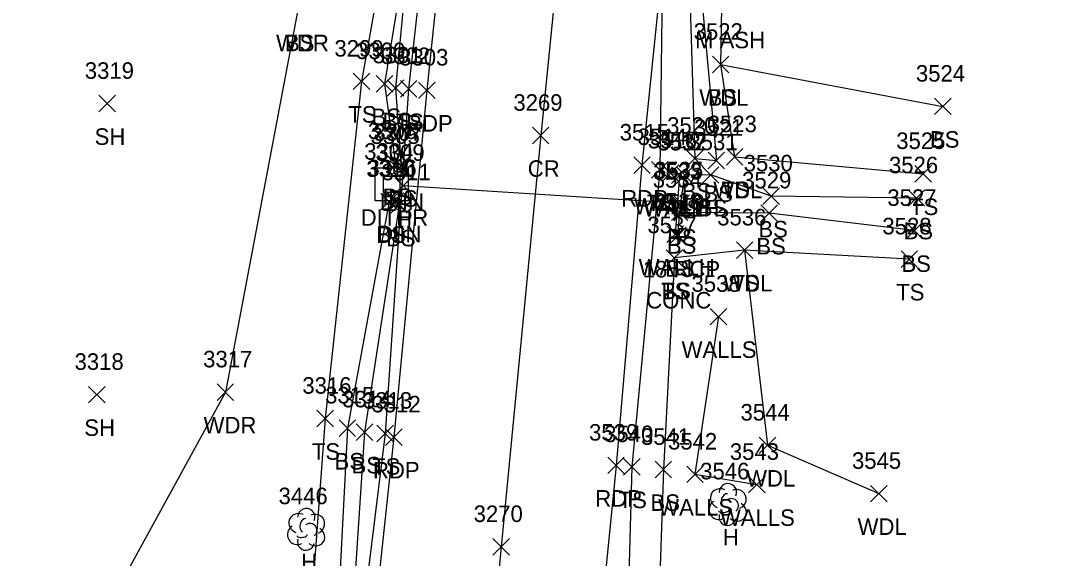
# Model space of a CAD drawing. Extents: x 1678863 to 1683592, y 407783 to 418211.
# Drawn here: x 1680318.1 to 1680442.9, y 414605.2 to 414670.3 of the extents above; entities that cross this region are included whole.
import ezdxf

# ---------------------------------------------------------------- set-up
doc = ezdxf.new("R2010")
doc.units = 0
for name, color, linetype in [('D_A', 7, 'Continuous'), ('D_C', 7, 'Continuous'), ('D_I', 7, 'Continuous'), ('D_TIC', 7, 'Continuous'), ('DCP', 7, 'Continuous'), ('DHW', 7, 'Continuous'), ('DS', 7, 'Continuous'), ('L_A', 7, 'Continuous'), ('L_C', 7, 'Continuous'), ('L_I', 7, 'Continuous'), ('L_TIC', 7, 'Continuous'), ('LAWA', 7, 'Continuous'), ('LELB', 7, 'Continuous'), ('LTD', 7, 'Continuous'), ('LWS', 7, 'Continuous'), ('P_A', 7, 'Continuous'), ('P_I', 7, 'Continuous'), ('P_TIC', 7, 'Continuous'), ('PET', 7, 'Continuous'), ('PRC', 7, 'Continuous')]:
    doc.layers.add(name, color=color, linetype=linetype)

msp = doc.modelspace()

# ---------------------------------------------------------------- linework, layer by layer
at = {"layer": 'D_TIC'}
for points in [[(1680362.81, 414651.36), (1680364.81, 414653.36)], [(1680364.81, 414651.36), (1680362.81, 414653.36)], [(1680395.77, 414650.82), (1680397.77, 414652.82)], [(1680397.77, 414650.82), (1680395.77, 414652.82)], [(1680396.87, 414650.57), (1680398.87, 414652.57)], [(1680398.87, 414650.57), (1680396.87, 414652.57)], [(1680363.4, 414649.31), (1680365.4, 414651.31)], [(1680365.4, 414649.31), (1680363.4, 414651.31)], [(1680362.5, 414647.45), (1680364.5, 414649.45)], [(1680364.5, 414647.45), (1680362.5, 414649.45)], [(1680397.05, 414647.2), (1680399.05, 414649.2)], [(1680399.05, 414647.2), (1680397.05, 414649.2)], [(1680396.32, 414643.43), (1680398.32, 414645.43)], [(1680398.32, 414643.43), (1680396.32, 414645.43)]]:
    msp.add_lwpolyline(points, dxfattribs=at)
at = {"layer": 'DCP'}
msp.add_lwpolyline([(1680364.4, 414650.31), (1680398.05, 414648.2)], dxfattribs=at)
at = {"layer": 'DHW'}
msp.add_lwpolyline([(1680396.77, 414651.82), (1680397.87, 414651.57), (1680397.32, 414644.43)], dxfattribs=at)
at = {"layer": 'DS'}
for p, q in [((1680361.02, 414652.47), (1680365.02, 414652.47)), ((1680361.02, 414648.47), (1680361.03, 414652.47)), ((1680365.02, 414652.47), (1680365.02, 414648.47)), ((1680362.02, 414651.47), (1680364.02, 414651.47)), ((1680362.02, 414649.47), (1680362.02, 414651.47)), ((1680364.02, 414651.47), (1680364.02, 414649.47)), ((1680364.02, 414649.47), (1680362.02, 414649.47)), ((1680363.02, 414650.48), (1680363.02, 414650.48)), ((1680365.02, 414648.47), (1680361.02, 414648.47)), ((1680363.52, 414648.47), (1680364.02, 414648.47))]:
    msp.add_line(p, q, dxfattribs=at)
at = {"layer": 'L_TIC'}
for points in [[(1680401.83, 414663.98), (1680403.83, 414665.98)], [(1680403.83, 414663.98), (1680401.83, 414665.98)], [(1680401.83, 414663.98), (1680403.83, 414665.98)], [(1680403.83, 414663.98), (1680401.83, 414665.98)], [(1680358.36, 414661.94), (1680360.36, 414663.94)], [(1680360.36, 414661.94), (1680358.36, 414663.94)], [(1680361.15, 414661.64), (1680363.15, 414663.64)], [(1680363.15, 414661.64), (1680361.15, 414663.64)], [(1680362.48, 414661.13), (1680364.48, 414663.13)], [(1680364.48, 414661.13), (1680362.48, 414663.13)], [(1680364.07, 414661.04), (1680366.07, 414663.04)], [(1680366.07, 414661.04), (1680364.07, 414663.04)], [(1680327.58, 414659.25), (1680329.58, 414661.25)], [(1680329.58, 414659.25), (1680327.58, 414661.25)], [(1680428.73, 414658.91), (1680430.73, 414660.91)], [(1680430.73, 414658.91), (1680428.73, 414660.91)], [(1680398.71, 414652.6), (1680400.71, 414654.6)], [(1680400.71, 414652.6), (1680398.71, 414654.6)], [(1680401.32, 414652.35), (1680403.32, 414654.35)], [(1680403.32, 414652.35), (1680401.32, 414654.35)], [(1680401.32, 414652.35), (1680403.32, 414654.35)], [(1680403.32, 414652.35), (1680401.32, 414654.35)], [(1680403.53, 414652.79), (1680405.53, 414654.79)], [(1680405.53, 414652.79), (1680403.53, 414654.79)], [(1680403.53, 414652.79), (1680405.53, 414654.79)], [(1680405.53, 414652.79), (1680403.53, 414654.79)], [(1680362.48, 414651.96), (1680364.48, 414653.96)], [(1680364.48, 414651.96), (1680362.48, 414653.96)], [(1680362.48, 414651.96), (1680364.48, 414653.96)], [(1680364.48, 414651.96), (1680362.48, 414653.96)], [(1680363.15, 414651.75), (1680365.15, 414653.75)], [(1680365.15, 414651.75), (1680363.15, 414653.75)], [(1680394.48, 414651.23), (1680396.48, 414653.23)], [(1680396.48, 414651.23), (1680394.48, 414653.23)], [(1680397.48, 414650.58), (1680399.48, 414652.58)], [(1680399.48, 414650.58), (1680397.48, 414652.58)], [(1680400.63, 414650.6), (1680402.63, 414652.6)], [(1680402.63, 414650.6), (1680400.63, 414652.6)], [(1680426.35, 414650.75), (1680428.35, 414652.75)], [(1680428.35, 414650.75), (1680426.35, 414652.75)], [(1680361.72, 414647.37), (1680363.72, 414649.37)], [(1680363.72, 414647.37), (1680361.72, 414649.37)], [(1680361.72, 414647.37), (1680363.72, 414649.37)], [(1680363.72, 414647.37), (1680361.72, 414649.37)], [(1680407.96, 414648.04), (1680409.96, 414650.04)], [(1680409.96, 414648.04), (1680407.96, 414650.04)], [(1680425.53, 414647.81), (1680427.53, 414649.81)], [(1680427.53, 414647.81), (1680425.53, 414649.81)], [(1680362.91, 414646.96), (1680364.91, 414648.96)], [(1680364.91, 414646.96), (1680362.91, 414648.96)], [(1680396.88, 414646.07), (1680398.88, 414648.07)], [(1680398.88, 414646.07), (1680396.88, 414648.07)], [(1680396.88, 414646.07), (1680398.88, 414648.07)], [(1680398.88, 414646.07), (1680396.88, 414648.07)], [(1680396.88, 414646.07), (1680398.88, 414648.07)], [(1680398.88, 414646.07), (1680396.88, 414648.07)], [(1680396.92, 414647.04), (1680398.92, 414649.04)], [(1680398.92, 414647.04), (1680396.92, 414649.04)], [(1680407.71, 414645.98), (1680409.71, 414647.98)], [(1680409.71, 414645.98), (1680407.71, 414647.98)], [(1680425.27, 414643.86), (1680427.27, 414645.86)], [(1680427.27, 414643.86), (1680425.27, 414645.86)], [(1680396.67, 414643.27), (1680398.67, 414645.27)], [(1680398.67, 414643.27), (1680396.67, 414645.27)], [(1680404.74, 414641.49), (1680406.74, 414643.49)], [(1680406.74, 414641.49), (1680404.74, 414643.49)], [(1680404.74, 414641.49), (1680406.74, 414643.49)], [(1680406.74, 414641.49), (1680404.74, 414643.49)], [(1680396.23, 414640.55), (1680398.23, 414642.55)], [(1680398.23, 414640.55), (1680396.23, 414642.55)], [(1680396.23, 414640.55), (1680398.23, 414642.55)], [(1680398.23, 414640.55), (1680396.23, 414642.55)], [(1680424.67, 414640.41), (1680426.67, 414642.41)], [(1680426.67, 414640.41), (1680424.67, 414642.41)], [(1680401.57, 414633.45), (1680403.57, 414635.45)], [(1680403.57, 414633.45), (1680401.57, 414635.45)], [(1680326.33, 414624), (1680328.33, 414626)], [(1680328.33, 414624), (1680326.33, 414626)], [(1680341.89, 414624.3), (1680343.89, 414626.3)], [(1680343.89, 414624.3), (1680341.89, 414626.3)], [(1680353.96, 414621.11), (1680355.96, 414623.11)], [(1680355.96, 414621.11), (1680353.96, 414623.11)], [(1680356.66, 414619.93), (1680358.66, 414621.93)], [(1680358.66, 414619.93), (1680356.66, 414621.93)], [(1680358.73, 414619.46), (1680360.73, 414621.46)], [(1680360.73, 414619.46), (1680358.73, 414621.46)], [(1680361.24, 414619.3), (1680363.24, 414621.3)], [(1680363.24, 414619.3), (1680361.24, 414621.3)], [(1680407.5, 414617.86), (1680409.5, 414619.86)], [(1680409.5, 414617.86), (1680407.5, 414619.86)], [(1680391.09, 414615.25), (1680393.09, 414617.25)], [(1680393.09, 414615.25), (1680391.09, 414617.25)], [(1680394.9, 414614.92), (1680396.9, 414616.92)], [(1680396.9, 414614.92), (1680394.9, 414616.92)], [(1680398.73, 414614.35), (1680400.73, 414616.35)], [(1680400.73, 414614.35), (1680398.73, 414616.35)], [(1680406.21, 414613.1), (1680408.21, 414615.1)], [(1680408.21, 414613.1), (1680406.21, 414615.1)], [(1680420.99, 414612.01), (1680422.99, 414614.01)], [(1680422.99, 414612.01), (1680420.99, 414614.01)]]:
    msp.add_lwpolyline(points, dxfattribs=at)
at = {"layer": 'LAWA'}
for points in [[(1680346.13, 414813.09), (1680361.24, 414798.08), (1680358.15, 414762.13), (1680352.6, 414699.48), (1680351.66, 414671.59), (1680342.89, 414625.3), (1680326.29, 414594.94), (1680318.11, 414579.07)], [(1680631.22, 414748.81), (1680599.57, 414760.95), (1680549.03, 414780.72), (1680516.79, 414791.82), (1680486.46, 414799.02), (1680463.26, 414805.73), (1680421.05, 414793.75), (1680414.74, 414758.81), (1680411.4, 414716.9), (1680407.3, 414688.75), (1680403.02, 414676.63), (1680402.83, 414664.98), (1680404.53, 414653.79)], [(1680405.74, 414642.49), (1680408.5, 414618.86), (1680421.99, 414613.01)]]:
    msp.add_lwpolyline(points, dxfattribs=at)
at = {"layer": 'LELB'}
for points in [[(1680364.43, 414906.77), (1680387.48, 414902.03), (1680389.89, 414894.72), (1680384.34, 414862.07), (1680378.6, 414830.99), (1680367.31, 414796.98), (1680365.18, 414762.53), (1680366.14, 414696.6), (1680365.44, 414682.92), (1680363.48, 414662.13), (1680364.15, 414652.75), (1680363.48, 414652.96)], [(1680412.63, 414818.89), (1680415.09, 414806.01), (1680412.16, 414786.48), (1680409.85, 414759.09), (1680404.3, 414724.04), (1680399.02, 414676), (1680399.71, 414653.6), (1680402.32, 414653.35)], [(1680404.3, 414724.04), (1680400.26, 414675.92), (1680402.32, 414653.35)], [(1680365.31, 414696.28), (1680359.36, 414662.94), (1680354.96, 414622.11), (1680352.91, 414594.29), (1680349.79, 414558.4), (1680346.87, 414517.57), (1680339.69, 414510.19), (1680319.96, 414508.09)], [(1680368.9, 414696.35), (1680365.07, 414662.04), (1680362.24, 414620.3), (1680358.93, 414593.47), (1680356.73, 414558.21), (1680353.79, 414516.76)], [(1680365.44, 414682.92), (1680362.15, 414662.64), (1680363.48, 414652.96)], [(1680395.79, 414677.26), (1680395.48, 414652.23), (1680392.09, 414616.25), (1680390.92, 414573.96), (1680393.54, 414543.92), (1680404.15, 414537.64), (1680415.65, 414535.59)], [(1680402.83, 414664.98), (1680429.73, 414659.91)], [(1680404.53, 414653.79), (1680427.35, 414651.75)], [(1680426.53, 414648.81), (1680408.96, 414649.04), (1680401.63, 414651.6), (1680398.48, 414651.58), (1680397.92, 414648.04), (1680397.88, 414647.07)], [(1680362.72, 414648.37), (1680357.66, 414620.93), (1680356.26, 414593.79), (1680353.52, 414558.2), (1680348.38, 414513.04)], [(1680362.72, 414648.37), (1680363.91, 414647.96), (1680359.73, 414620.46), (1680357.97, 414593.52), (1680355.51, 414558.23), (1680350.93, 414512.65)], [(1680397.67, 414644.27), (1680397.88, 414647.07)], [(1680426.27, 414644.86), (1680408.71, 414646.98), (1680397.88, 414647.07)], [(1680425.67, 414641.41), (1680405.74, 414642.49), (1680397.23, 414641.55)], [(1680397.23, 414641.55), (1680395.9, 414615.92), (1680394.32, 414569.06), (1680396.45, 414551.9), (1680405.53, 414542.86), (1680418.02, 414540.79)]]:
    msp.add_lwpolyline(points, dxfattribs=at)
at = {"layer": 'LTD'}
for p, q in [((1680403.67, 414611.74), (1680403.67, 414611.74)), ((1680403.67, 414611.74), (1680403.67, 414611.74)), ((1680352.65, 414608.73), (1680352.65, 414608.73)), ((1680352.65, 414608.73), (1680352.65, 414608.73))]:
    msp.add_line(p, q, dxfattribs=at)
for centre in [(1680403.72, 414613.17), (1680352.69, 414610.17)]:
    msp.add_arc(centre, 1.05, 335.5272, 180.9563, dxfattribs=at)
for centre, major_axis, ratio, start_param, end_param in [((1680402.88, 414612.4), (1.21, -0.51), 0.895232, 1.570796, 4.712389), ((1680404.71, 414612.32), (-1.14, -0.48), 0.949671, 1.570796, 4.712389), ((1680402.59, 414611.03), (0.58, -1.04), 0.959034, 3.141593, 6.283185), ((1680403.46, 414612.2), (-0.208, -0.792), 0.645439, 3.141593, 6.283185), ((1680404.17, 414611.57), (-0.5, 0.667), 0.989748, 3.141593, 6.283185), ((1680351.86, 414609.4), (1.21, -0.51), 0.895232, 1.570796, 4.712389), ((1680353.69, 414609.32), (-1.14, -0.48), 0.949671, 1.570796, 4.712389), ((1680403.21, 414610.99), (-0.625, -0.083), 0.423636, 0, 3.141593), ((1680404.67, 414610.9), (-1.09, 0.79), 0.841452, 1.570796, 4.712389), ((1680352.44, 414609.19), (-0.208, -0.792), 0.645439, 3.141593, 6.283185), ((1680353.15, 414608.57), (-0.5, 0.667), 0.989748, 3.141593, 6.283185), ((1680403.67, 414610.24), (0.26, 1.06), 0.942809, 1.570796, 4.712389), ((1680351.56, 414608.02), (0.58, -1.04), 0.959034, 3.141593, 6.283185), ((1680353.65, 414607.9), (-1.09, 0.79), 0.841452, 1.570796, 4.712389), ((1680352.65, 414607.23), (0.26, 1.06), 0.942809, 1.570796, 4.712389), ((1680352.19, 414607.98), (-0.625, -0.083), 0.423636, 0, 3.141593)]:
    msp.add_ellipse(centre, major_axis=major_axis, ratio=ratio, start_param=start_param, end_param=end_param, dxfattribs=at)
at = {"layer": 'LWS'}
msp.add_lwpolyline([(1680402.57, 414634.45), (1680399.73, 414615.35), (1680407.21, 414614.1)], dxfattribs=at)
at = {"layer": 'P_TIC'}
for points in [[(1680366.27, 414660.86), (1680368.27, 414662.86)], [(1680368.27, 414660.86), (1680366.27, 414662.86)], [(1680380.06, 414655.38), (1680382.06, 414657.38)], [(1680382.06, 414655.38), (1680380.06, 414657.38)], [(1680392.31, 414651.78), (1680394.31, 414653.78)], [(1680394.31, 414651.78), (1680392.31, 414653.78)], [(1680362.27, 414618.85), (1680364.27, 414620.85)], [(1680364.27, 414618.85), (1680362.27, 414620.85)], [(1680389.17, 414615.43), (1680391.17, 414617.43)], [(1680391.17, 414615.43), (1680389.17, 414617.43)], [(1680375.28, 414605.57), (1680377.28, 414607.57)], [(1680377.28, 414605.57), (1680375.28, 414607.57)]]:
    msp.add_lwpolyline(points, dxfattribs=at)
at = {"layer": 'PET'}
for points in [[(1680468.22, 415214.69), (1680459.71, 415182.46), (1680453.72, 415158.31), (1680446.09, 415129.91), (1680440.19, 415107.06), (1680428.11, 415053.84), (1680423.8, 415033.84), (1680420.13, 415016.1), (1680415.53, 414995.95), (1680407.02, 414954.69), (1680401.79, 414930.3), (1680395.67, 414897.37), (1680389.91, 414860.31), (1680385.22, 414829.17), (1680382.27, 414805.05), (1680376.74, 414757.64), (1680370.82, 414695.91), (1680367.27, 414661.86), (1680363.27, 414619.85), (1680360.41, 414593.08), (1680357.32, 414558.18), (1680353.79, 414516.76), (1680349.58, 414483.99)], [(1680495.8, 415211.55), (1680487.74, 415180.8), (1680478.66, 415148.16), (1680471.94, 415120.07), (1680462.57, 415079.59), (1680454.69, 415044.69), (1680445.65, 415004.54), (1680436.54, 414962.49), (1680430.18, 414933.71), (1680423.61, 414897.47), (1680418.44, 414869.8), (1680415.44, 414847.01), (1680410.82, 414817.35), (1680406.85, 414787.83), (1680404.02, 414758.7), (1680400.52, 414722.33), (1680395.79, 414677.26), (1680393.31, 414652.78), (1680390.17, 414616.43), (1680385.57, 414569.94), (1680383.24, 414550.06), (1680381.08, 414523.52), (1680377.37, 414484.42)]]:
    msp.add_lwpolyline(points, dxfattribs=at)
at = {"layer": 'PRC'}
msp.add_lwpolyline([(1680481.59, 415211.17), (1680473.06, 415178.67), (1680464.71, 415146.4), (1680454.43, 415103.39), (1680442.46, 415051.38), (1680433.87, 415013.05), (1680427.71, 414986.46), (1680420.88, 414953.3), (1680415, 414925.91), (1680408.48, 414889.99), (1680403.43, 414856.87), (1680399.05, 414826.29), (1680394.79, 414790.7), (1680390.07, 414747.8), (1680385.23, 414697.92), (1680381.06, 414656.38), (1680376.28, 414606.57), (1680371.5, 414556.43), (1680367.38, 414511.69), (1680362.63, 414458.59)], dxfattribs=at)

# ---------------------------------------------------------------- texts
at = {"layer": 'D_A'}
for s, p in [('DIIN', (1680361.58, 414647.36)), ('WALLH', (1680392.36, 414646.82)), ('WALLH', (1680393.47, 414646.57)), ('DITHR', (1680359.27, 414645.45)), ('P', (1680363.78, 414645.31)), ('DIIN', (1680361.27, 414643.45)), ('P', (1680397.43, 414643.2)), ('WALLH', (1680392.91, 414639.43))]:
    msp.add_text(s, height=2, dxfattribs=at).set_placement(p)
at = {"layer": 'D_C'}
for s, p in [('18 RCP', (1680393.41, 414639.2)), ('CONC', (1680393.83, 414635.43))]:
    msp.add_text(s, height=2, dxfattribs=at).set_placement(p)
at = {"layer": 'D_I'}
for s, p in [('3305', (1680360.47, 414655.36)), ('3516', (1680394.02, 414654.82)), ('3517', (1680395.18, 414654.57)), ('3304', (1680359.7, 414653.45)), ('3309', (1680361.06, 414653.31)), ('3306', (1680360.1, 414651.45)), ('3535', (1680394.79, 414651.2)), ('3518', (1680394.63, 414647.43))]:
    msp.add_text(s, height=2, dxfattribs=at).set_placement(p)
at = {"layer": 'L_A'}
for s, p in [('WDR', (1680349.03, 414666.59)), ('BS', (1680350.1, 414666.59)), ('WDL', (1680400.25, 414659.98)), ('BS', (1680401.27, 414659.98)), ('TS', (1680357.77, 414657.94)), ('BS', (1680360.59, 414657.64)), ('BS', (1680361.92, 414657.13)), ('TS', (1680363.48, 414657.04)), ('SH', (1680327.07, 414655.25)), ('BS', (1680428.17, 414654.91)), ('BS', (1680398.15, 414648.6)), ('WDL', (1680401.95, 414648.79)), ('TS', (1680402.94, 414648.79)), ('BS', (1680361.93, 414647.96)), ('BS', (1680361.93, 414647.96)), ('BS', (1680362.6, 414647.75)), ('BS', (1680400.76, 414648.35)), ('BS', (1680400.76, 414648.35)), ('TS', (1680393.89, 414647.23)), ('BS', (1680396.92, 414646.58)), ('BS', (1680400.07, 414646.6)), ('TS', (1680425.76, 414646.75)), ('BS', (1680407.4, 414644.04)), ('BS', (1680424.97, 414643.81)), ('BS', (1680361.16, 414643.37)), ('BS', (1680361.16, 414643.37)), ('BS', (1680362.35, 414642.96)), ('BS', (1680396.36, 414643.04)), ('BS', (1680396.32, 414642.07)), ('BS', (1680396.32, 414642.07)), ('BS', (1680396.32, 414642.07)), ('BS', (1680407.15, 414641.98)), ('BS', (1680424.71, 414639.86)), ('BS', (1680396.11, 414639.27)), ('WDL', (1680403.15, 414637.49)), ('TS', (1680404.15, 414637.49)), ('TS', (1680395.64, 414636.55)), ('BS', (1680395.67, 414636.55)), ('TS', (1680424.08, 414636.41)), ('WALLS', (1680398.11, 414629.45)), ('SH', (1680325.82, 414620)), ('WDR', (1680340.26, 414620.3)), ('TS', (1680353.36, 414617.11)), ('BS', (1680356.11, 414615.93)), ('BS', (1680358.17, 414615.46)), ('TS', (1680360.65, 414615.3)), ('WDL', (1680405.92, 414613.86)), ('TS', (1680390.49, 414611.25)), ('BS', (1680394.34, 414610.92)), ('WALLS', (1680395.28, 414610.35)), ('WALLS', (1680402.75, 414609.1)), ('WDL', (1680419.41, 414608.01)), ('H', (1680403.1, 414606.74)), ('H', (1680352.08, 414603.73))]:
    msp.add_text(s, height=2, dxfattribs=at).set_placement(p)
at = {"layer": 'L_C'}
msp.add_text('M ASH', height=2, dxfattribs=at).set_placement((1680399.74, 414666.95))
at = {"layer": 'L_I'}
for s, p in [('3522', (1680399.57, 414667.98)), ('3522', (1680399.57, 414667.98)), ('3299', (1680356.09, 414665.94)), ('3300', (1680358.72, 414665.64)), ('3301', (1680360.71, 414665.13)), ('3302', (1680361.73, 414665.04)), ('3319', (1680325.88, 414663.25)), ('3524', (1680426.47, 414662.91)), ('3520', (1680396.36, 414656.6)), ('3521', (1680399.62, 414656.35)), ('3521', (1680399.62, 414656.35)), ('3523', (1680401.27, 414656.79)), ('3523', (1680401.27, 414656.79)), ('3308', (1680360.15, 414655.96)), ('3308', (1680360.15, 414655.96)), ('3307', (1680360.82, 414655.75)), ('3514', (1680392.79, 414655.23)), ('3525', (1680424.09, 414654.75)), ('3532', (1680395.22, 414654.58)), ('3531', (1680398.94, 414654.6)), ('3310', (1680359.94, 414651.37)), ('3310', (1680359.94, 414651.37)), ('3533', (1680394.66, 414651.04)), ('3530', (1680405.62, 414652.04)), ('3526', (1680423.21, 414651.81)), ('3311', (1680361.79, 414650.96)), ('3534', (1680394.62, 414650.07)), ('3534', (1680394.62, 414650.07)), ('3534', (1680394.62, 414650.07)), ('3529', (1680405.44, 414649.98)), ('3519', (1680394.97, 414647.27)), ('3527', (1680423.01, 414647.86)), ('3536', (1680402.42, 414645.49)), ('3536', (1680402.42, 414645.49)), ('3537', (1680393.97, 414644.55)), ('3537', (1680393.97, 414644.55)), ('3528', (1680422.41, 414644.41)), ('3538', (1680399.31, 414637.45)), ('3318', (1680324.64, 414628)), ('3317', (1680340.2, 414628.3)), ('3316', (1680352.21, 414625.11)), ('3315', (1680354.97, 414623.93)), ('3314', (1680357.03, 414623.46)), ('3313', (1680359.55, 414623.3)), ('3544', (1680405.24, 414621.86)), ('3540', (1680388.74, 414619.25)), ('3541', (1680393.2, 414618.92)), ('3542', (1680396.47, 414618.35)), ('3543', (1680403.95, 414617.1)), ('3545', (1680418.73, 414616.01)), ('3546', (1680400.36, 414614.74)), ('3446', (1680349.33, 414611.73))]:
    msp.add_text(s, height=2, dxfattribs=at).set_placement(p)
at = {"layer": 'P_A'}
for s, p in [('RDP', (1680364.76, 414656.86)), ('CR', (1680379.49, 414651.38)), ('RDP', (1680390.8, 414647.78)), ('RDP', (1680360.76, 414614.85)), ('RDP', (1680387.66, 414611.43))]:
    msp.add_text(s, height=2, dxfattribs=at).set_placement(p)
at = {"layer": 'P_I'}
for s, p in [('3303', (1680363.93, 414664.86)), ('3269', (1680377.75, 414659.38)), ('3515', (1680390.62, 414655.78)), ('3312', (1680360.58, 414622.85)), ('3539', (1680386.91, 414619.43)), ('3270', (1680372.94, 414609.57))]:
    msp.add_text(s, height=2, dxfattribs=at).set_placement(p)

doc.saveas('drawing.dxf')
